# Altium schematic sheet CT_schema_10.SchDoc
size 274 x 160 mm
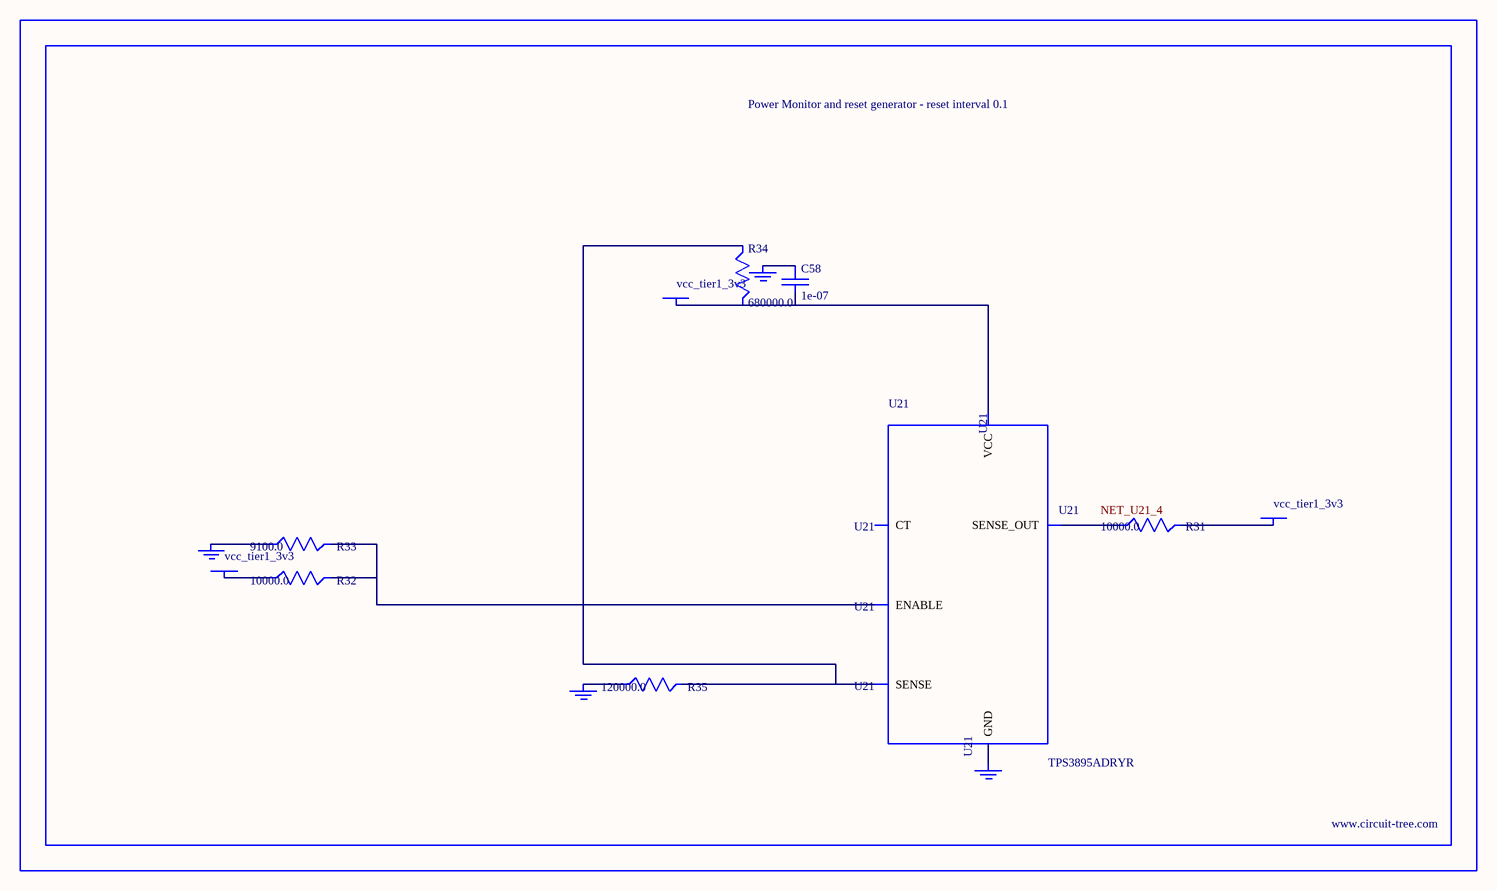
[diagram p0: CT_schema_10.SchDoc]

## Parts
BORDER9  (no value)
C58  1e-07  [C0402]
GND_INSTANCE_9_0  (no value)
GND_INSTANCE_9_1  (no value)
GND_INSTANCE_9_2  (no value)
GND_INSTANCE_9_3  (no value)
POWER_INSTANCE_9_0  vcc_tier1_3v3
POWER_INSTANCE_9_1  vcc_tier1_3v3
POWER_INSTANCE_9_2  vcc_tier1_3v3
R31  10000.0  [R0603]
R32  10000.0  [R0603]
R33  9100.0  [R0603]
R34  680000.0  [R0603]
R35  120000.0  [R0603]
U21  TPS3895ADRYR  [SON-6]

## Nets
NetC58_1: C58.1 GND_INSTANCE_9_2.0(GND)
NetC58_2: C58.2 POWER_INSTANCE_9_2.0(PWR) R34.2 U21.6(VCC)
NetGND_INSTANCE_9_0_0: GND_INSTANCE_9_0.0(GND) R33.1
NetGND_INSTANCE_9_1_0: GND_INSTANCE_9_1.0(GND) R35.1
NetGND_INSTANCE_9_3_0: GND_INSTANCE_9_3.0(GND) U21.2(GND)
NetPOWER_INSTANCE_9_0_0: POWER_INSTANCE_9_0.0(PWR) R32.1
NetPOWER_INSTANCE_9_1_0: POWER_INSTANCE_9_1.0(PWR) R31.2
NetR31_1: R31.1 U21.4(SENSE_OUT)
NetR32_2: R32.2 R33.2 U21.1(ENABLE)
NetR34_1: R34.1 R35.2 U21.3(SENSE)

Not connected (* = marked no-connect by the designer): U21 5(CT)

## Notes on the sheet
- Labels drawn without touching a wire or pin: NET_U21_4

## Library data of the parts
BORDER9 = BORDER_PAGE9
C58 = C0402C104K3RACTU
GND_INSTANCE_9_0-GND_INSTANCE_9_3 = GND
POWER_INSTANCE_9_0-POWER_INSTANCE_9_2 = PWR
R31 R32 = RC0603JR-0710KL
R33 = RC0603JR-079K1L
R34 = RC0603JR-07680KL
R35 = RC0603JR-07120KL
